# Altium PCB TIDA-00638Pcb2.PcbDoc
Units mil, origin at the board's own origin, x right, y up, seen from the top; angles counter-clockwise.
Board outline 1170 x 1290 mil, 4 copper layers (Top Layer, PowerLayer, GroundLayer, Bottom Layer), stack 84.834 mil thick; 44 components, 25 nets, 119 pads, 41 vias.
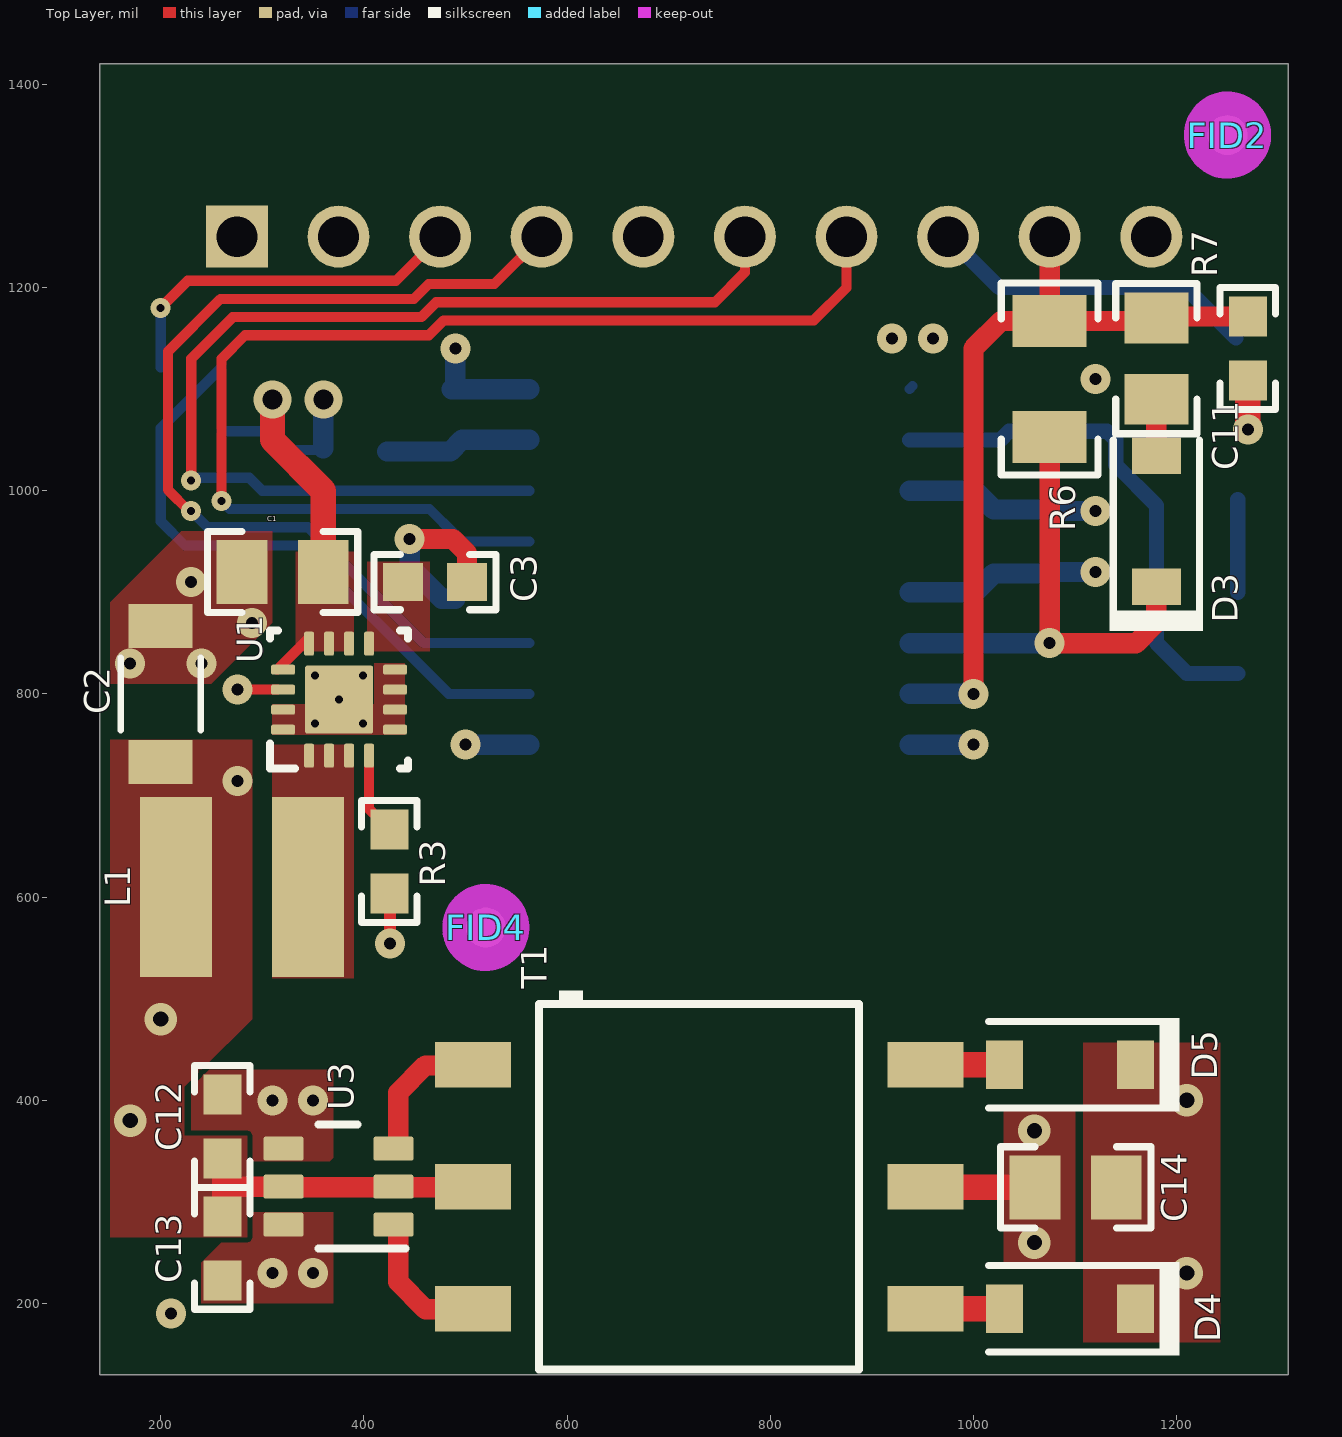
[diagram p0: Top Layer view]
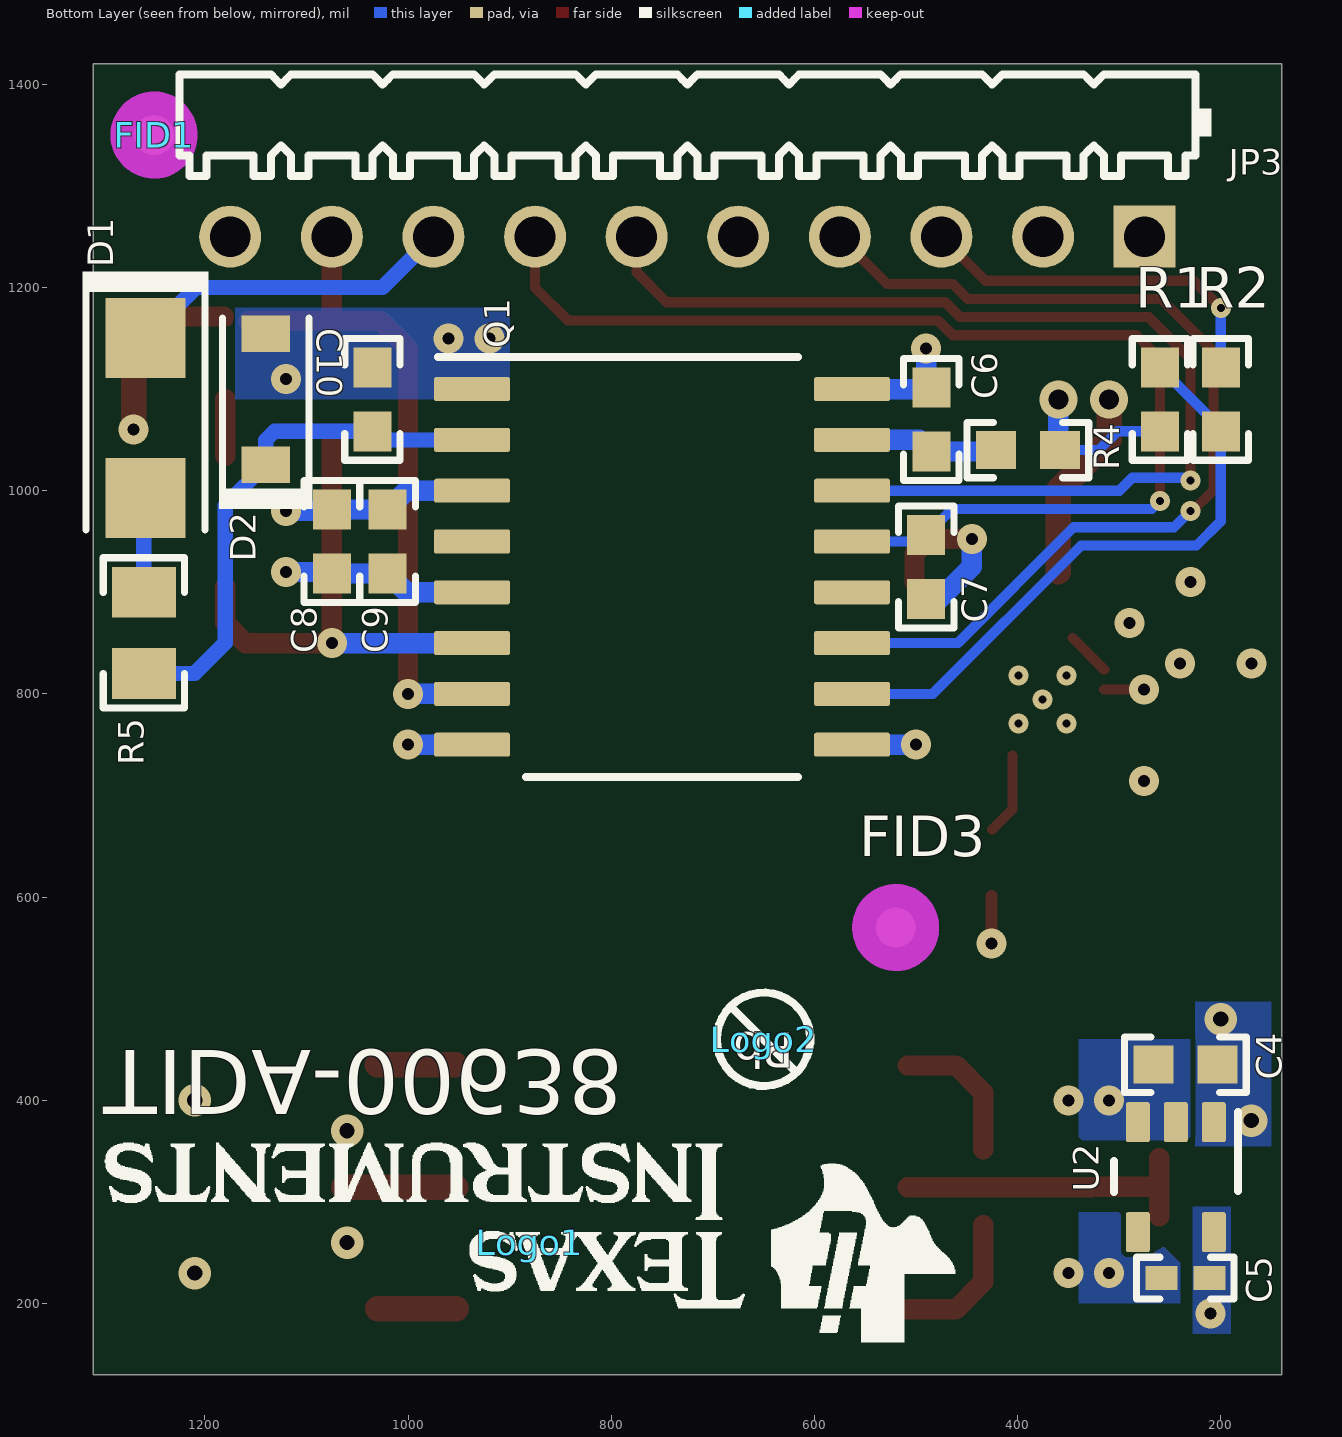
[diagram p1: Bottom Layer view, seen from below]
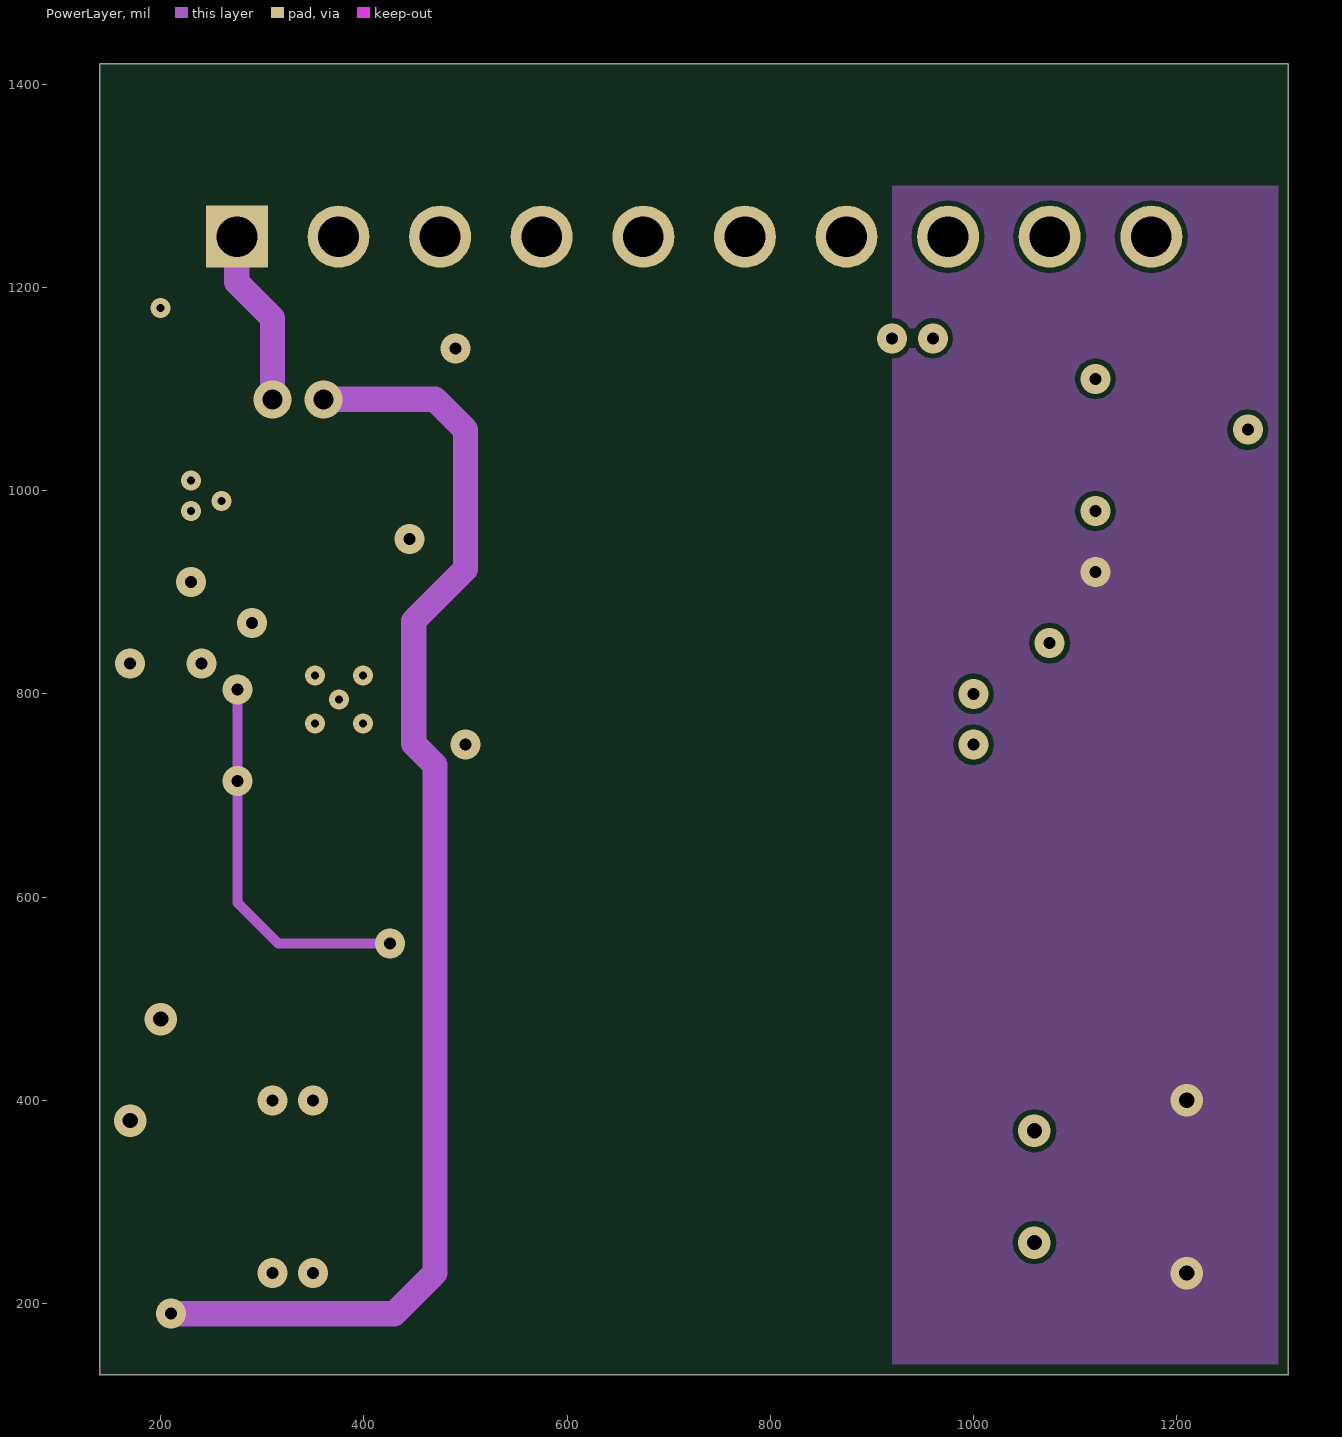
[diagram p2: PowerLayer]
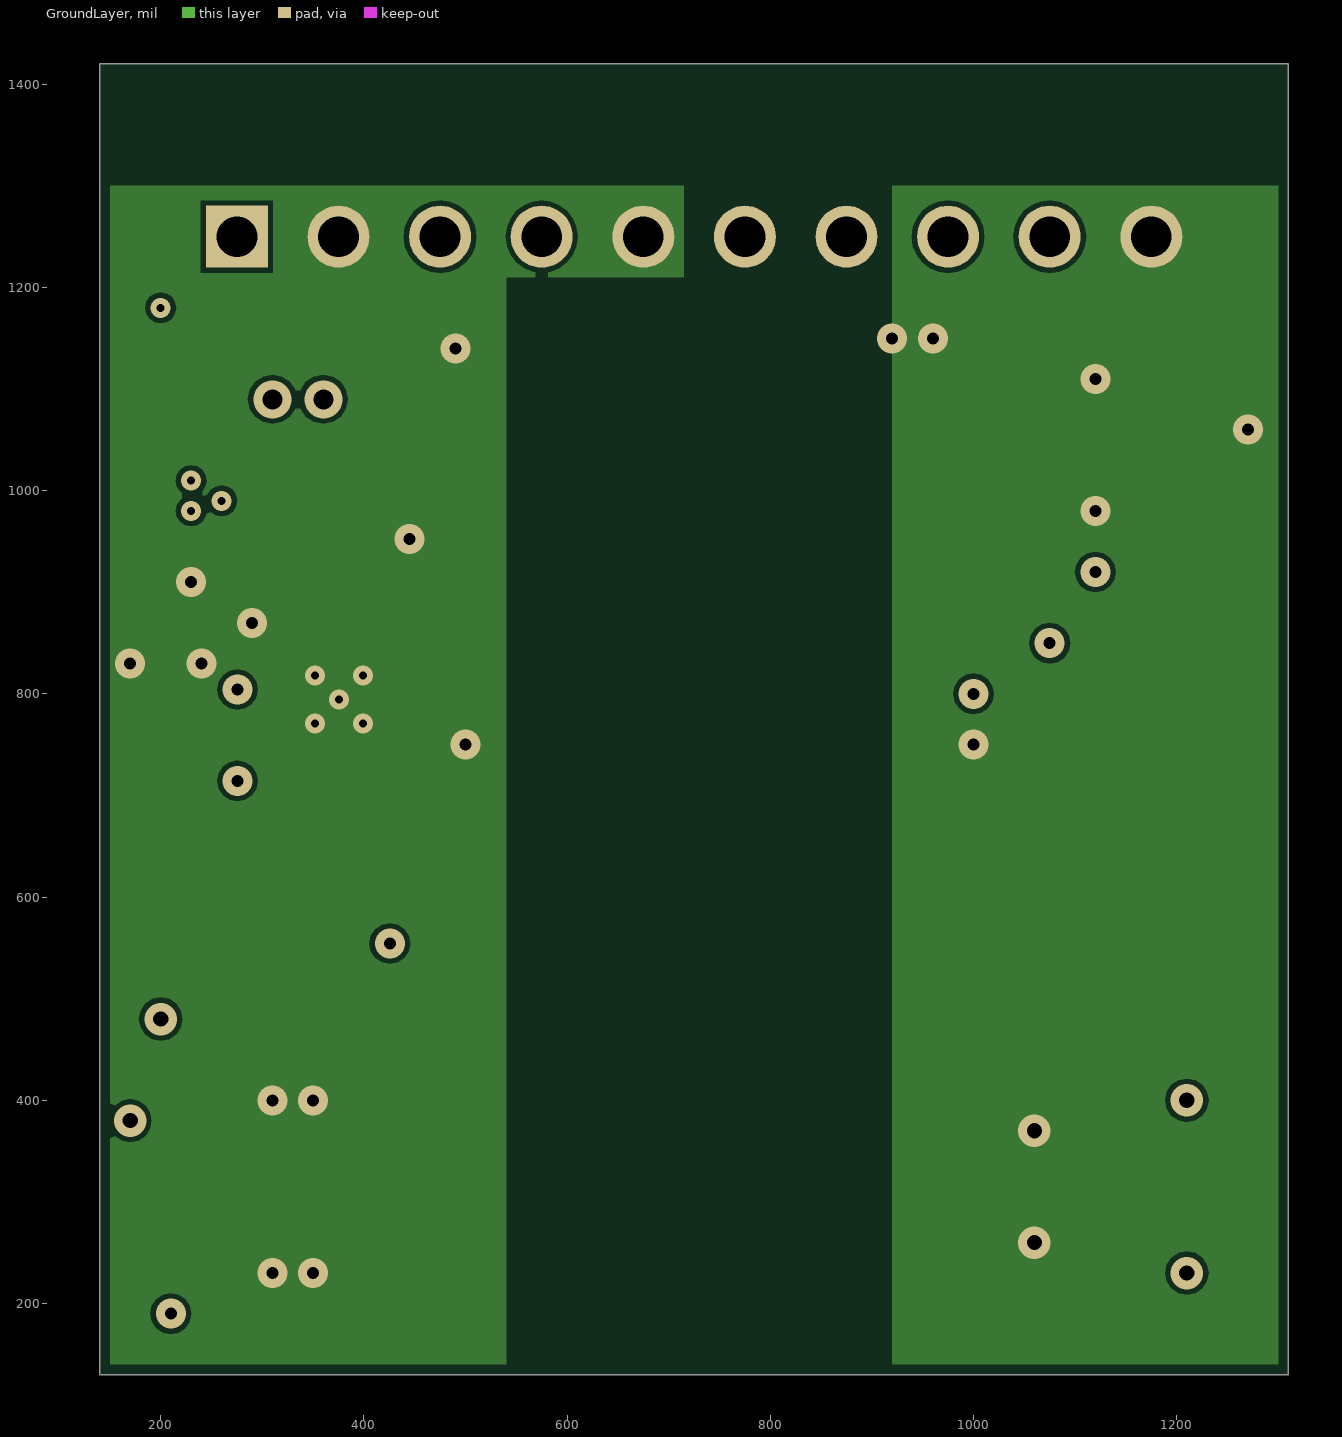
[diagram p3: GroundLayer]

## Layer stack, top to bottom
Top Solder: solder mask 0.4, Solder Resist, Dk 3.5
Top Layer: signal copper 1.4
Dielectric 2: dielectric 10, Dk 4.2
PowerLayer: signal copper 1.417
Dielectric1: core 59.2, FR-4, Dk 4.8
GroundLayer: signal copper 1.417
Dielectric 3: dielectric 10, Dk 4.2
Bottom Layer: signal copper 1.4
Bottom Solder: solder mask 0.4, Solder Resist, Dk 3.5

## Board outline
140,130 1310,130 1310,1420 140,1420

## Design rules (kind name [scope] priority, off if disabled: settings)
AcuteAngle [All] p1: minimum=4.50000000000000E+0001 checktracksonly=FALSE
AssemblyTestPointUsage [All] p1: valid=2
BoardOutlineClearance BoardOutlineClearance_MountingHoles [OnCopper and InComponentClass('Mounting Holes')] p1: gap=10
BoardOutlineClearance BoardOutlineClearance_Poly [OnCopper and IsPoly] p2: gap=10
BoardOutlineClearance [OnCopper and Not InComponentClass('Logo') and not InComponentClass('FiducialMark') and not InRegion(1000,500,4000,800) and not InPoly] p3: gap=10
Clearance Clearance_Keepouts [((IsTrack Or IsArc) And Not InPoly) And IsFree and IsKeepOut vs ((IsTrack Or IsArc) And Not InPoly) And IsFree and IsKeepOut] p1: gap=0
Clearance Clearance_Poly [InPolygon] p2: gap=5
Clearance [All] p3: gap=7.87
ComponentClearance ComponentClearance_MountingHoles_FiducialMarks [InComponentClass('Mounting Holes') vs InComponentClass('FiducialMark')] p1: gap=50 collisioncheckmode=3 verticalgap=10 showdistances=FALSE
ComponentClearance ComponentClearance_Shunt [InComponentClass('Header') vs InComponentClass('Shunt')] p2: gap=0 collisioncheckmode=3 verticalgap=0 showdistances=FALSE
ComponentClearance ComponentClearance_Logo [InComponentClass('Logo')] p3: gap=50 collisioncheckmode=3 verticalgap=10 showdistances=FALSE
ComponentClearance ComponentClearance_ScrewToNut [(HasFootprint('NY PMS 440 0025 PH')) vs (HasFootprint('Keystone_1902C'))] p4: gap=5 collisioncheckmode=3 verticalgap=10 showdistances=FALSE
ComponentClearance ComponentClearance_MountingHoles [InComponentClass('Mounting Holes')] p5: gap=250 collisioncheckmode=3 verticalgap=100000 showdistances=FALSE
ComponentClearance ComponentClearance_SmallPassives [HasFootprint('0201*') or HasFootprint('0402*') or HasFootprint('0508') or HasFootprint('0603*') or HasFootprint('0612') or HasFootprint('0805*') or HasFootprint('0815*') or HasFootprint('0830*') or HasFootprint('1206*') or HasFootprint('1210*') or HasFootprint('1808*') or HasFootprint('1812*') or HasFootprint('1825*') or HasFootprint('2010*') or HasFootprint('2220*') or HasFootprint('2225*') or HasFootprint('2512*') or HasFootprint('2728*') or HasFootprint('3518*') vs HasFootprint('0201*') or HasFootprint('0402*') or HasFootprint('0508') or HasFootprint('0603*') or HasFootprint('0612') or HasFootprint('0805*') or HasFootprint('0815*') or HasFootprint('0830*') or HasFootprint('1206*') or HasFootprint('1210*') or HasFootprint('1808*') or HasFootprint('1812*') or HasFootprint('1825*') or HasFootprint('2010*') or HasFootprint('2220*') or HasFootprint('2225*') or HasFootprint('2512*') or HasFootprint('2728*') or HasFootprint('3518*')] p6: gap=14.96 collisioncheckmode=3 verticalgap=10 showdistances=FALSE
ComponentClearance ComponentClearance_THtoSMT [IsThruComponent vs IsSMTComponent] p7: gap=40 collisioncheckmode=3 verticalgap=30 showdistances=FALSE
ComponentClearance ComponentClearance_THtoTH [IsThruComponent vs IsThruComponent] p8: gap=30 collisioncheckmode=3 verticalgap=30 showdistances=FALSE
ComponentClearance [All] p9: gap=30 collisioncheckmode=3 verticalgap=10 showdistances=FALSE
DiffPairsRouting [All] p1: maxlimit=100 minlimit=10 mostfreqgap=10 toplayer_minwidth=15 toplayer_maxwidth=15 toplayer_prefwidth=15 midlayer1_minwidth=15 midlayer1_maxwidth=15 midlayer1_prefwidth=15 midlayer2_minwidth=15 midlayer2_maxwidth=15 midlayer2_prefwidth=15 bottomlayer_minwidth=15 bottomlayer_maxwidth=15 bottomlayer_prefwidth=15 maxuncoupledlength=1000
FabricationTestPointUsage TestPointUsage [All] p1: valid=2 allowmultiple=FALSE
FabricationTestpoint Testpoint [All] p1: side=3 testpointundercomponent=TRUE minsize=40 maxsize=100 preferedsize=60 minholesize=0 maxholesize=40 preferedholesize=32 testpointgrid=1 allowsidetop=TRUE allowsidebottom=TRUE usegrid=TRUE gridtolerance=0.01
FanoutControl Fanout_LCC [IsLCC] p1: bgadir=Out bgaviamode=Centered fanoutstyle=Auto fanoutdirection=Alternating viagrid=1 // Fanout_LCC (Default Rule)
FanoutControl Fanout_BGA [IsBGA] p2: bgadir=Out bgaviamode=Centered fanoutstyle=Auto fanoutdirection=Alternating viagrid=1 // Fanout_BGA (Default Rule)
FanoutControl Fanout_Default [All] p4: bgadir=Out bgaviamode=Centered fanoutstyle=Auto fanoutdirection=Alternating viagrid=1 // Fanout_Default (Default Rule)
FanoutControl Fanout_Small [(CompPinCount < 5)] p5: bgadir=Out bgaviamode=Centered fanoutstyle=Auto fanoutdirection=OutThenIn viagrid=1 // Fanout_Small (Default Rule)
HoleSize [All] p1: absolutevalues=TRUE maxlimit=251 minlimit=7.87 maxpercent=80.000 minpercent=20.000
MinimumAnnularRing MinimumAnnularRing_ThermalPadVias [IsVia and InAnyComponent] p1: minimumring=5.91
MinimumAnnularRing [All] p2: minimumring=8
MinimumSolderMaskSliver MinimumSolderMaskSliver_Logo [InComponentClass('Logo') vs InComponentClass('Logo')] p1: minsoldermaskwidth=0.7
MinimumSolderMaskSliver [All] p2: minsoldermaskwidth=3.94
PlaneConnect [All] p1: planeconnectstyle=Direct reliefexpansion=10 reliefentries=4 reliefconductorwidth=10 reliefairgap=10
PolygonConnect [All] p1: connectstyle=Direct reliefconductorwidth=10 reliefentries=4 polygonreliefangle="90 Angle" airgapwidth=10
RoutingVias ThermalPadVias [IsVia and InAnyComponent] p1: holewidth=7.87 width=19.68 viastyle="Through Hole" minholewidth=7.87 minwidth=19.68 maxholewidth=12.99 maxwidth=23.62
RoutingVias [All] p2: holewidth=16 width=34 viastyle="Through Hole" minholewidth=7.87 minwidth=26 maxholewidth=40 maxwidth=65
SilkToBoardRegionClearance [Not ((IsComment or IsDesignator) And (Hide <> 'False')) and not InRegion(1000,500,4000,800)] p1:
SilkToSilkClearance SilkToSilkClearance_Pb-FreeLogo [(HasFootprint('Pb-Free_Overlay_Medium') OR HasFootprint('Pb-Free_Overlay_Small')) vs (HasFootprint('Pb-Free_Overlay_Medium') OR HasFootprint('Pb-Free_Overlay_Small'))] p1: silktosilkclearance=0
SilkToSilkClearance [All] p2: silktosilkclearance=4
SilkToSolderMaskClearance SilkToComponentPadClearance [(IsPad or IsFill or IsRegion) and InAnycomponent] p1: minsilkscreentomaskgap=5 clearancetoexposedcopper=TRUE
SilkToSolderMaskClearance "Silk to Solder Mask Opening" [All] p2: minsilkscreentomaskgap=4 clearancetoexposedcopper=FALSE
SolderMaskExpansion [All] p1: expansion=1.97
Width [All] p1: maxlimit=100 minlimit=6 preferedwidth=10 checkconnectedcopper=TRUE
15 further rules are at their usual default settings.

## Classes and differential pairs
component class Header: JP3
component class TIDA-00638Sch: C1 C2 C3 C4 C5 C6 C7 C8 C9 C10 C11 C12 C13 C14 D1 D2 D3 D4 D5 JP3 L1 Q1 R1 R2 R3 R4 R5 R6 R7 T1 U1 U2 U3
component class Logo: Logo1
component class EVM_Hardware: FID1 FID2 FID4 Logo1 Logo2 Logo3 ZZ1 ZZ2 ZZ3 ZZ4
component class FiducialMark: FID1 FID2 FID4
component class AssemblyNote: ZZ1 ZZ2 ZZ3 ZZ4

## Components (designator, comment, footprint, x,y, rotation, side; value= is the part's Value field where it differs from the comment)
C1 "GRM219R61E106KA12D" 0805_HV 320,920 r180 top
C2 "GRM31CR61A226KE19L" 1206_180 200,800 r90 top
C3 "GRM188R71E332KA01D" 0603#1 470,910 r0 top
C4 "CL10B105KQ8NNNC" 0603#1 235,435 r0 bottom
C5 "CL05A225KQ5NNNC" 0402 235,225 r0 bottom
C6 "C1608X7R1H104K080AA" 0603#1 485,1070 r90 bottom
C7 "06035A220JAT2A" 0603#1 490,925 r270 bottom
C8 "C1608X7R1H104K080AA" 0603#1 1075,950 r90 bottom
C9 "C1608X7R1V105K080AC" 0603#1 1020,950 r90 bottom
C10 "06035A221FAT2A" 0603#2 1410,1410 r180 bottom
C11 "GRM188R71H104KA93D" 0603#1 1270,1140 r270 top
C12 "GRM188R71H104KA93D" 0603#1 260.59,374.33 r90 top
C13 "C1608X5R1A106M080AC" 0603#1 260.59,254.33 r270 top
C14 "GRM21BR6YA106KE43L" 0805_HV 1100.59,314.33 r180 top
D1 "STTH112A" SMA 1258.46,1071.54 r270 bottom
D2 "1N5819HW-7-F" SOD-123 1140,1090 r90 bottom
D3 "1N5819HW-7-F" SOD-123 1180,970 r90 top
D4 "MBR0540T1G" SOD-123 1095,194.92 r180 top
D5 "MBR0540T1G" SOD-123 1095,435.08 r180 top
FID1 "Fiducial" Fiducial10-20 1250,1350 r180 bottom
FID2 "Fiducial" Fiducial10-20 1250,1350 r0 top
FID3 "Fiducial" Fiducial10-20 520,570 r180 bottom
FID4 "Fiducial" Fiducial10-20 520,570 r0 top
JP3 "TSW-110-08-T-S-RA" Samtec_TSW-110-08-x-S-RA 725,1250 r0 bottom
L1 "SDR0403-2R2ML" SDR0403 280,610 r180 top
Logo1 "Texas Instruments" TI_Stacked_Overlay_Small 880,260 r0 bottom
Logo2 "Pb-Free Symbol" Pb-Free_Overlay_Small 650,460 r0 bottom
Logo3 "FCC disclaimer" FCC_disclaimer 2350,3380 r0 top
Q1 "ISO5451DWR" DW0016B_N 750,925 r180 bottom
R1 "CRCW06030000Z0EA" 0603#1 260,1090 r270 bottom
R2 "CRCW06030000Z0EA" 0603#1 200,1090 r270 bottom
R3 "CRCW0603100KJNEA" 0603#1 425,635 r270 top
R4 "RC0603FR-0710RL" 0603#1 390,1040 r0 bottom
R5 "CRCW08051K00JNEA" 0805_HV 1260,860 r90 bottom
R6 "RC1206FR-074R7L" 1206 1075,1110 r90 top
R7 "RC0805JR-074R7L" 0805_HV 1180,1130 r90 top
T1 "750342879" Wurth_750342879 730,315 r0 top
U1 "TPS62143RGTT" RGT0016C 375.59,794.33 r90 top
U2 "TPS70633DBVR" DBV0005A_N 244.33,324.41 r270 bottom
U3 "SN6505ADBVR" DBV0006A_N 375,315 r180 top
ZZ1 "This Assembly Note is for PCB labels only" AssemblyNoteLabel 185,3938 r0 top
ZZ2 "These assemblies are ESD sensitive, ESD precautions shall be observed." AssemblyNote 185,3829.11 r0 top
ZZ3 "These assemblies must be clean and free from flux and all contaminants. Use of no clean flux is not acceptable." AssemblyNote 185,3740.56 r0 top
ZZ4 "These assemblies must comply with workmanship standards IPC-A-610 Class 2, unless otherwise specified." AssemblyNote 185,3652 r0 top

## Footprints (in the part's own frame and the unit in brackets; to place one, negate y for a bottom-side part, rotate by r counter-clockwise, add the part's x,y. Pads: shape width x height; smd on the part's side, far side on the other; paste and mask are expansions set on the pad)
0402 [mm] "0402 from SM-752 data"
  rect 0.8x0.6 smd: 1(-0.6,0) 2(0.6,0)
  silkscreen extent -1.22,-0.52 1.22,0.52, body extent -0.55,-0.3 0.55,0.3, height 0.6
0603#1 [mm] "0603 from SM-752 data"
  rect 1x0.95 smd: 1(-0.8,0) 2(0.8,0)
  silkscreen extent -1.52,-0.69 1.52,0.69, body extent -0.87,-0.47 0.87,0.47, height 1
0603#2 [mm] "0603 from SM-752 data"
  rect 0.95x1 smd: 1(9.525,-8.928) 2(9.525,-7.328)
  silkscreen extent 8.83,-9.65 10.22,-6.6, body extent 9.05,-9 10,-7.25, height 1
0805_HV [mil] "0805 with 30mil clearance between pads"
  rect 50x63 smd: 1(-40,0) 2(40,0)
  silkscreen extent -74,-40 74,40, body extent -43,-29 43,29, height 57
1206 [mm] "1206 from SM-752 data"
  rect 1.3x1.85 smd: 1(-1.45,0) 2(1.45,0)
  silkscreen extent -2.4,-1.21 2.4,1.21, body extent -1.7,-0.9 1.7,0.9, height 1.35
1206_180 [mm] "1206_180"
  rect 1.1x1.6 smd: 1(-1.7,0) 2(1.7,0)
  silkscreen extent -0.9,-1 0.9,1, body extent -1.75,-0.95 1.75,0.95, height 1.8
AssemblyNote [mil] "Assembly Note"
AssemblyNoteLabel [mil] "Assembly Note for PCB Labels"
DBV0005A_N [mm] "SOT23, 5-Leads, Body 2.9x1.6mm, Pitch 0.95mm, Lead Span 2.8mm, IPC Medium Density"
  rrect17% 1x0.6 smd: 1(-1.375,0.95) 2(-1.375,0) 3(-1.375,-0.95) 4(1.375,-0.95) 5(1.375,0.95)
  silkscreen extent -1.63,-1.55 0.38,1.55, body extent -1.42,-1.46 1.42,1.46, height 1.09
DBV0006A_N [mm] "SOT23, 6-Leads, Body 2.9x1.6mm, Pitch 0.95mm, Lead Span 2.8mm, IPC Medium Density"
  rrect17% 1x0.6 smd: 1(-1.375,0.95) 2(-1.375,0) 3(-1.375,-0.95) 4(1.375,-0.95) 5(1.375,0) 6(1.375,0.95)
  silkscreen extent -1.68,-1.55 0.5,1.55, body extent -1.42,-1.46 1.42,1.46, height 1.12
DW0016B_N [mm] "SOIC, 16-Leads, Body 10.5x7.6mm, Pitch 1.27mm, IPC Medium Density"
  rrect17% 1.9x0.6 smd: 1(-4.75,4.445) 2(-4.75,3.175) 3(-4.75,1.905) 4(-4.75,0.635) 5(-4.75,-0.635) 6(-4.75,-1.905) 7(-4.75,-3.175) 8(-4.75,-4.445) 9(4.75,-4.445) 10(4.75,-3.175) 11(4.75,-1.905) 12(4.75,-0.635) 13(4.75,0.635) 14(4.75,1.905) 15(4.75,3.175) 16(4.75,4.445)
  silkscreen extent -5.6,-5.25 3.4,5.25, body extent -5.17,-5.15 5.17,5.15, height 2.59
FCC_disclaimer [mil]
Fiducial10-20 [mm]
  round 1 smd mask+0.5: 1(0,0)
  Top Layer keep-out circle w1.178: c0,0 r0.5
Pb-Free_Overlay_Small [mil]
  silkscreen extent -46,-46 46,46
RGT0016C [mm] "QFN, 16-Leads, Body 3x3mm, Pitch 0.5mm, Thermal Pad 1.7x1.7mm, TI Recommended"
  rrect40% 0.6x0.25 smd: 1(-1.4,0.75) 2(-1.4,0.25) 3(-1.4,-0.25) 4(-1.4,-0.75) 9(1.4,-0.75) 10(1.4,-0.25) 11(1.4,0.25) 12(1.4,0.75)
  rrect40% 0.25x0.6 smd: 5(-0.75,-1.4) 6(-0.25,-1.4) 7(0.25,-1.4) 8(0.75,-1.4) 13(0.75,1.4) 14(0.25,1.4) 15(-0.25,1.4) 16(-0.75,1.4)
  rrect6% 1.55x1.55 on Top Paste: 17(0,0)
  rrect6% 1.7x1.7 smd paste-0.85: 17(0,0)
  silkscreen extent -1.72,-1.73 1.72,1.73, body extent -1.57,-1.57 1.58,1.58, height 1.01
Samtec_TSW-110-08-x-S-RA [mm] "Header, 2.54mm, 10x1, R/A, TH"
  rect 1.55x1.55 hole 1.02: 1(-11.43,0)
  round 1.55 hole 1.02: 2(-8.89,0) 3(-6.35,0) 4(-3.81,0) 5(-1.27,0) 6(1.27,0) 7(3.81,0) 8(6.35,0) 9(8.89,0) 10(11.43,0)
  silkscreen extent -13.1,-4.06 12.7,-1.52, body extent -12.7,-9.9 12.7,0.32, height 3.02
SDR0403 [mm] "BOURNS"
  rect 1.8x4.5 smd: 1(-1.65,0) 2(1.65,0)
  body extent -2.4,-2.4 2.4,2.4, height 3.3
SMA [mm] "Molded Diode, 2-Leads, Body 4.3x2.6mm, IPC Medium Density, based on OnSemi component dimensions and land pattern"
  rect 2x2 smd: 1(-2,0) 2(2,0)
  silkscreen extent -3.66,-1.57 2.79,1.57, body extent -2.6,-1.3 2.6,1.3, height 2.42
SOD-123 [mm] "On Semi recommended land pattern"
  rect 0.915x1.22 smd: 1(-1.637,0) 2(1.637,0)
  silkscreen extent -2.74,-1.17 2.03,1.17, body extent -1.93,-0.9 1.93,0.9, height 1.35
TI_Stacked_Overlay_Small [mil]
  silkscreen extent -418,-98 418,98
Wurth_750342879 [mm] "SMD, 6-Leads, Body 9.14x8mm, Pitch 3.05mm"
  rect 1.9x1.14 smd: 1(-5.655,3.05) 2(-5.655,0) 3(-5.655,-3.05) 4(5.655,-3.05) 5(5.655,0) 6(5.655,3.05)
  silkscreen extent -4,-4.57 4,4.9, body extent -6.35,-4.57 6.35,4.57, height 7.83

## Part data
C1: "CAP, CERM, 10 µF, 25 V, +/- 10%, X5R, 0805"
C2: "CAP, CERM, 22 µF, 10 V, +/- 10%, X5R, 1206"
C3: "CAP, CERM, 3300 pF, 25 V, +/- 10%, X7R, 0603"
C4: "CAP, CERM, 1 µF, 6.3 V, +/- 10%, X7R, 0603"
C5: "CAP, CERM, 2.2 µF, 6.3 V, +/- 10%, X5R, 0402"
C6 C8 C11 C12: "CAP, CERM, 0.1 µF, 50 V, +/- 10%, X7R, 0603"
C7: "CAP, CERM, 22 pF, 50 V, +/- 5%, C0G/NP0, 0603"
C9: "CAP, CERM, 1 µF, 35 V, +/- 10%, X7R, 0603"
C10: "CAP, CERM, 220 pF, 50 V, +/- 1%, C0G/NP0, 0603"
C13: "CAP, CERM, 10 µF, 10 V, +/- 20%, X5R, 0603"
C14: "CAP, CERM, 10 µF, 35 V, +/- 10%, X5R, 0805"
D1: "Diode, Ultrafast, 1200 V, 1 A, SMA"
D2 D3: "Diode, Schottky, 40 V, 1 A, SOD-123"
D4 D5: "Diode, Schottky, 40 V, 0.5 A, SOD-123"
FID1 FID2 FID3 FID4: "Fiducial mark.  There is nothing to buy or mount."
JP3: "Header, 2.54mm, 10x1, Tin, R/A, TH"
L1: "Inductor, Drum Core, Ferrite, 2.2 µH, 2.6 A, 0.047 ohm, SMD"
Logo1: library part TI_Logo, "Texas Instrument Corporate Signature"
Logo2: library part Pb-Free
Logo3: library part FCC_disclaimer, "FCC_disclaimer"
Q1: "High-CMTI 2.5-A / 5-A Isolated IGBT, MOSFET Gate Driver with Active Safety Features, DW0016B (SOIC-16)"
R1 R2: "RES, 0, 5%, 0.1 W, 0603"
R3: "RES, 100 k, 5%, 0.1 W, 0603"
R4: "RES, 10.0, 1%, 0.1 W, 0603"
R5: "RES, 1.0 k, 5%, 0.125 W, 0805"
R6: "RES, 4.70, 1%, 0.25 W, 1206"
R7: "RES, 4.7, 5%, 0.125 W, 0805"
T1: "Transformer, 50 uH, SMT"
U1: "Buck Step Down Regulator with 3 to 17 V Input and 5 V Output, -40 to 85 degC, 16-Pin QFN (RGT), Green (RoHS & no Sb/Br)"
U2: "150-mA, 6.5-V, 1-uA IQ Voltage Regulators with Enable, DBV0005A (SOT-5)"
U3: "Low-Noise 1-A Transformer Driver for Isolated Power Supplies, Internal Clock-160kHz, DBV0006A (SOT-6)"
ZZ1: library part AssemblyNoteLabel
ZZ2 ZZ3 ZZ4: library part AssemblyNote

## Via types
v1: diameter 29.53, hole 11.81, Top Layer to Bottom Layer, 24 vias
v2: diameter 32, hole 15, Top Layer to Bottom Layer, 6 vias
v3: diameter 19.68, hole 7.87, Top Layer to Bottom Layer, tented top, 5 vias
v4: diameter 19.68, hole 7.87, Top Layer to Bottom Layer, 4 vias
v5: diameter 37.4, hole 19.68, Top Layer to Bottom Layer, 2 vias

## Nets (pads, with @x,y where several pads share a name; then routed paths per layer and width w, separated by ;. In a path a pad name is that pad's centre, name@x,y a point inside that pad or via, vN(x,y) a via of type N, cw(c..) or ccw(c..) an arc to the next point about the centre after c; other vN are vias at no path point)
+3V3: C5.1 R1.2 R4.1 U2.5 | length 1445.6
  PowerLayer w25: v1(210,190) 430,190 470,230 470,730 449,751 449,871.76 500,922.76 500,1060 470,1090 v5(360,1090)
  Bottom Layer w10: R1.2 301.5,1058.5 320,1040 R4.1 R4.1@360,1041.5
  Bottom Layer w20: R4.1@360,1041.5 v5(360,1090)
+5V: C2.1 C4.1 C12.1 C13.1 L1.2 R3.2 T1.2 U1.14 U2.1 U3.2 U3.5 | length 760.3
  Top Layer w10: v1(275.59,804.33) 275.75,804.17 U1.14@314.76,804.17
  Top Layer w12: v1(425.59,554.33) R3.2@425.59,600.87
  Top Layer w20: C13.1 C12.1 ; 260.59,315 U3.5 ; U3.5@327.44,314.33 T1.2@508.09,314.33
  PowerLayer w10: v1(275.59,804.33) v1(275.59,714.33) 275.59,594.33 315.59,554.33 v1(425.59,554.33)
  other v2: 170,380 200,480
+15V: C1.1 JP3.1 U1.10 U1.11 U1.12 U1.13 | length 409.5
  Top Layer w10: U1.13@314.76,823.86 U1.12@346.06,855.16
  Top Layer w25: v5(310,1090) 310,1050 360,1000 C1.1
  PowerLayer w25: JP3.1 275,1205 310,1170 v5(310,1090)
+15VI: C8.1 C9.1 C14.1 D4.1 D5.1 Q1.5 | length 191.3
  Bottom Layer w10: C8.1@1070,918.5 C8.1@1071.5,920
  Bottom Layer w20: Q1.5 1001.5,900 C9.1 C8.1@1070,918.5 ; C8.1@1071.5,920 v1(1120,920)
  other v2: 1210,230 1210,400
DESAT: C10.1 D2.1 Q1.2 R5.1 | length 519
  Bottom Layer w15: Q1.2 1026.5,1050 C10.1 1131.5,1058.5 1140,1050 D2.1 1180,985.53 1180,850 1210,820 R5.1
FAULT: C7.1 JP3.7 Q1.13 | length 1153.7
  Top Layer w10: v4(260,990) 260,1130 282.99,1152.99 463.91,1152.99 478.55,1167.64 842.86,1167.64 875,1199.78 JP3.7
  Bottom Layer w10: v4(260,990) 268,982 464.5,982 C7.1 496.5,950 Q1.13
GND: C1.2 C2.2 C3.2 C4.2 C5.2 C6.2 C7.2 C12.2 C13.2 JP3.2 JP3.5 Q1.9 Q1.16 U1.5 U1.6 U1.7 U1.8 U1.15 U1.16 U1.17@375.59,794.33 U2.2 U2.3 U3.4 U3.6 | length 357.3
  Top Layer w20: v1(445,952.5) 487.5,952.5 501.5,938.5 C3.2
  Bottom Layer w10: C6.2@486.5,1100 C6.2@490,1103.5
  Bottom Layer w20: v1(445,952.5) 445,925 476.5,893.5 C7.2 ; C6.2@486.5,1100 Q1.16 ; C6.2@490,1103.5 v1(490,1140) ; v1(500,750) Q1.9
  other v1: 310,230 350,230 310,400 350,400 170,830 240,830 290,870 230,910
  other v3: 351.97,770.71 399.21,770.71 375.59,794.33 351.97,817.95 399.21,817.95
GNDI: C8.2 C9.2 C10.2 C11.2 C14.2 D2.2 JP3.10 Q1.1 Q1.3 Q1.8 T1.5 | length 417.1
  Top Layer w25: T1.5@953.09,314.33 C14.2@1063.19,314.33 ; v1(1270,1060) C11.2
  Bottom Layer w10: Q1.1 Q1.1@940,1102.99 ; C8.2@1070,981.5 C8.2@1071.5,980
  Bottom Layer w20: Q1.8 v1(1000,750) ; Q1.3 1001.5,1000 C9.2 C8.2@1070,981.5 ; C8.2@1071.5,980 v1(1120,980)
  other v1: 1120,1110 920,1150 960,1150
  other v2: 1060,260 1060,370
GTDRV: C11.1 JP3.9 Q1.7 R6.2 R7.2 | length 746.8
  Top Layer w10: R7.2@1177.09,1167.09 R7.2
  Top Layer w20: v1(1000,800) 1000,1140 1027.09,1167.09 R6.2 ; JP3.9 R6.2 ; R7.2@1157.09,1167.09 R6.2 ; R7.2@1181.5,1171.5 C11.1
  Bottom Layer w20: Q1.7 v1(1000,800)
NetC3_1: C3.1 U1.9
NetC6_1: C6.1 Q1.15 R4.2 | length 146.9
  Bottom Layer w10: R4.2 R4.2@422.99,1038.5
  Bottom Layer w20: R4.2@422.99,1038.5 C6.1 496.5,1050 Q1.15
NetD1_2: D1.2 R5.2 | length 93.4
  Bottom Layer w10: D1.2 D1.2@1260,991.26
  Bottom Layer w15: R5.2 D1.2@1260,991.26
NetD3_2: D3.2 R7.1 | length 55.5
  Top Layer w20: D3.2 R7.1
NetD4_2: D4.2 T1.4 | length 77.1
  Top Layer w25: T1.4 D4.2@1029.78,194.92
NetD5_2: D5.2 T1.6 | length 77.3
  Top Layer w25: T1.6@953.23,435.08 D5.2
NetL1_1: L1.1 U1.1 U1.2 U1.3
NetR3_1: R3.1 U1.4 | length 81
  Top Layer w10: U1.4 405.12,686.38 R3.1
NetT1_1: T1.1 U3.3 | length 141.2
  Top Layer w20: U3.3@433.74,351.73 433.74,407.48 460.59,434.33 T1.1@508.09,434.33
NetT1_3: T1.3 U3.1 | length 141.2
  Top Layer w20: U3.1@433.74,276.93 433.74,221.18 460.59,194.33 T1.3@508.09,194.33
OUT: D3.1 Q1.6 R6.1 | length 489.7
  Top Layer w20: R6.1 v1(1075,850) 1160,850 1180,870 D3.1
  Bottom Layer w20: Q1.6 v1(1075,850)
PWM1: JP3.3 R2.1 | length 362.5
  Top Layer w10: v4(200,1180) 226.61,1206.61 431.61,1206.61 JP3.3
  Bottom Layer w10: R2.1 v4(200,1180)
PWM1.1: Q1.10 R1.1 R2.2 | length 609.8
  Bottom Layer w10: R1.1 200,1061.5 R2.2 200,970 223.87,946.13 337.42,946.13 483.54,800 Q1.10
PWM2: JP3.4 Q1.11 | length 969.2
  Top Layer w10: v4(230,980) 227.87,980 207.28,1000.59 207.28,1137.28 258.74,1188.74 449.1,1188.74 463.74,1203.39 528.39,1203.39 JP3.4
  Bottom Layer w10: v4(230,980) 246,964 345,964 459,850 Q1.11
QCOL: D1.1 JP3.8 | length 324.8
  Bottom Layer w15: JP3.8 1025,1200 1208.74,1200 D1.1
RST: JP3.6 Q1.14 | length 1074.6
  Top Layer w10: v4(230,1010) 230,1130 270.87,1170.87 456.5,1170.87 471.15,1185.51 745.51,1185.51 775,1215 JP3.6
  Bottom Layer w10: v4(230,1010) 232.72,1012.72 287.28,1012.72 300,1000 Q1.14
pads on no net: FID1.1 FID2.1 FID3.1 FID4.1 Q1.4 Q1.12 U1.17@375.59,794.33 U2.4

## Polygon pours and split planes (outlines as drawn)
GNDI on Top Layer "TOP_LAYER_GNDI_P038" (solid, remove dead copper, pour order 38): 1030,390 1100,390 1100,240 1030,240
NetL1_1 on Top Layer "TOP_LAYER_NETL1_1_P034" (solid, remove dead copper, pour order 34): 390,750 390,520 310,520 310,750
GND on Top Layer "Top-GND 2" (solid, remove dead copper, pour order 32): 230,340 370,340 370,430 230,430
GND on Top Layer "TOP_LAYER_GND_P030" (solid, remove dead copper, pour order 30): 240,200 370,200 370,290 290,290 240,240
GND on Top Layer "TOP_LAYER_GND_P026" (solid, remove dead copper, pour order 26): 250,810 150,810 150,890 220,960 310,960 310,870 280,840
+5V on Top Layer "Top-N$6" (solid, remove dead copper, pour order 14): 150,755 290,755 290,480 223.17,413.17 223.17,365 285,365 285,265 223.17,265 150,265
+15VI on Top Layer "Top-+15VI" (solid, remove dead copper, pour order 10): 1108.09,456.83 1243.09,456.83 1243.09,161.83 1108.09,161.83
NetC3_1 on Top Layer "Top-N$3" (solid, remove dead copper, pour order 4): 403.09,841.83 403.09,930 465,930 465,841.83
+15V on Top Layer "Top-+15V" (solid, remove dead copper, pour order 0): 390,841.83 390,940 333.09,940 333.09,841.83
GND on Top Layer "TOP_LAYER_GND_P040" (solid, remove dead copper, pour order 40): 310,760 310,790 340,790 410,790 410,830 440,830 440,760
GND on Bottom Layer "BOTTOM_LAYER_GND_P028" (solid, remove dead copper, pour order 28): 240,200 340,200 340,290 290,290 240,240
+5V on Bottom Layer "Top-+5V" (solid, remove dead copper, pour order 24): 225,496.96 225,355 195,355 150,355 150,496.96
+3V3 on Bottom Layer "Top-+3V3" (solid, remove dead copper, pour order 22): 190,170 190,295 227.5,295 227.5,170
GND on Bottom Layer "Top-GND 2" (solid, remove dead copper, pour order 20): 229.96,360.62 254.96,360.62 340,360.62 340,460 229.96,460
GNDI on Bottom Layer "BOTTOM_LAYER_GNDI_P042" (solid, remove dead copper, pour order 42): 900,1090 900,1180 1170,1180 1170,1090
GNDI on GroundLayer "Top-GNDI" (solid, remove dead copper, pour order 8): 1340,130 920,130 920,1300 1340,1300
GND on GroundLayer "Bottom-GND" (solid, remove dead copper, pour order 16): 140,1300 715,1300 715,1210 540,1210 540,130 140,130
+15VI on PowerLayer "Top-GNDI" (solid, remove dead copper, pour order 36): 1310,130 920,130 920,1300 1310,1300

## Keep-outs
Keep-Out Layer:
  text ".Layer_Name" at 577,-858.49 h60

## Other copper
Top Layer:
  text ".Layer_Name" at 577,-858.49 h60
Bottom Layer:
  text ".Layer_Name" at 577,-858.49 h60

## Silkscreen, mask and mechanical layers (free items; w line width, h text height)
Top Overlay:
  text ".Layer_Name" at 577,-858.49 h60
Bottom Overlay:
  text "TIDA-00638" at 1300,470 h108.27 r180
  text ".Layer_Name" at 577,-858.49 h60
Top Paste:
  text ".Layer_Name" at 577,-858.49 h60
Bottom Paste:
  text ".Layer_Name" at 577,-858.49 h60
Top Solder:
  text ".Layer_Name" at 577,-858.49 h60
  text ".Layer_Name" at 577,-858.49 h60
Bottom Solder:
  text ".Layer_Name" at 577,-858.49 h60
Drill Guide:
  text ".Layer_Name" at 577,-858.49 h60
M1 Board Outline:
  lines w10: 1340,1410 1340,0 0,0 0,1410 1340,1420
  text ".Layer_Name" at 577,-858.49 h60
M2 Board Dimensions:
  rectangle: 0,-275 125,-150
  rectangle: 125,-400 500,-275
  lines w7: 0,-275 1000,-275 ; 125,-400 125,-150 ; 250,-400 250,-150 ; 500,-400 500,-150 ; 750,-400 750,-150 ; 0,-400 1000,-400 1000,-150 0,-150 0,-400
  text ".Layer_Name" at 577,-858.49 h60
M3 3D STEP Top:
  text ".Layer_Name" at 577,-858.49 h60
M4 3D STEP Bottom:
  text ".Layer_Name" at 577,-858.49 h60
M5 Assembly Top:
  lines w10: -292,-930.17 6308,-930.17 ; -292,-726.83 6310,-726.83 ; -292,-523.5 -292,-1133.5 3713,-1133.5 6310,-1133.5 6310,-523.5 -291.5,-523.5 -291.5,-1133.5 1284,-1133.5 ; 2173,-1133.5 2173,-523.5 ; 3440,-726.83 3440,-523.5 ; 4280,-726.83 4280,-523.5 ; 4902,-1140 4902,-937.17
  text "COMPONENTS MARKED 'DNP' SHOULD NOT BE POPULATED." at 1153.5,-318.5 h60
  text "ASSEMBLY VARIANT:" at 1153,-434 h60
  text ".VariantName" at 2189,-434 h60
  text "PCB VIEWED FROM TOP SIDE" at -228.5,-655.67 h60
  text "BOARD #:" at 2248,-655.67 h60
  text ".PRJ_Number" at 2793.5,-655.67 h60
  text "REV:" at 3638,-655.67 h60
  text ".PCB_Rev" at 3929.5,-655.67 h60
  text "SVN REV:" at 4476,-655.67 h60
  text ".VersionControl_RevNumber" at 4982,-655.67 h60
  text "TID #:" at 2248,-859 h60
  text ".TID" at 2793.5,-859 h60
  text "PLOT NAME =" at -228.5,-1064.34 h60
  text ".plot_File_Name" at 577,-1064.34 h60
  text "GENERATED    :" at 2250,-1064.34 h60
  text ".Print_Date" at 3119.5,-1064.34 h60
  text ".Print_Time" at 3848.5,-1064.34 h60
  text "TEXAS INSTRUMENTS" at 5113,-1064.34 h60
M6 Assembly Bottom:
  lines w10: -292.5,-727.33 6309.5,-727.33 ; -290.5,-930.67 6309.5,-930.67 ; 1115.5,-1140.5 1115.5,-937.67 ; 1737.5,-727.33 1737.5,-524 ; 2577.5,-727.33 2577.5,-524 ; 3844.5,-1134 3844.5,-524 ; 4733.5,-1134 6309,-1134 6309,-524 -292.5,-524 -292.5,-1134 2304.5,-1134 6309.5,-1134 6309.5,-524
  text "COMPONENTS MARKED 'DNP' SHOULD NOT BE POPULATED." at 6102,-318 h60
  text ".VariantName" at 5058,-434 h60
  text "ASSEMBLY VARIANT:" at 6097,-434 h60
  text ".VersionControl_RevNumber" at 1035.5,-656.17 h60
  text "SVN REV:" at 1541.5,-656.17 h60
  text ".PCB_Rev" at 2088,-656.17 h60
  text "REV:" at 2379.5,-656.17 h60
  text ".PRJ_Number" at 3224,-656.17 h60
  text "BOARD #:" at 3769.5,-656.17 h60
  text "PCB VIEWED FROM BOTTOM SIDE" at 6246,-656.17 h60
  text ".TID" at 3224,-859.5 h60
  text "TID #:" at 3769.5,-859.5 h60
  text "TEXAS INSTRUMENTS" at 904.5,-1064.84 h60
  text ".Print_Time" at 2169,-1064.84 h60
  text ".Print_Date" at 2898,-1064.84 h60
  text "GENERATED    :" at 3767.5,-1064.84 h60
  text ".plot_File_Name" at 5440.5,-1064.84 h60
  text "PLOT NAME =" at 6246,-1064.84 h60
M9 Title Sheet:
  drawing of 57 lines, arcs and shapes, not listed
  text "1" at 739.84,8036.5 h70
  text "2" at 3235.5,8036.5 h70
  text "3" at 5724.84,8036.5 h70
  text "4" at 8231.51,8036.5 h70
  text "5" at 10730.5,8036.5 h70
  text "6" at 13235.5,8036.5 h70
  text "A" at -416.5,6893.5 h70
  text "A" at 14383.5,6893.5 h70
  text "B" at -416.5,4513.5 h70
  text "B" at 14383.5,4513.5 h70
  text "C" at -416.5,2138.5 h70
  text "C" at 14383.5,2138.5 h70
  text "PROJECT TITLE:" at 11343.5,277.5 h45
  text ".PRJ_Title" at 11393.5,144.17 h70
  text "DESIGNED FOR:" at 11343.5,-23.5 h45
  text ".PRJ_Customer" at 11393.5,-163.5 h70
  text "D" at -416.5,-231.5 h70
  text "D" at 14383.5,-231.5 h70
  text "FILE NAME:" at 11343.5,-323.5 h45
  text ".PCB_File_Name_No_Path" at 11393.5,-443.5 h70
  text "Texas Instruments (TI) and/or its licensors do not warrant the accuracy or completeness of this specification" at 6374,-605.34 h45
  text "ENGINEER:" at 11343.5,-613.5 h45
  text "LAYOUT BY:" at 12848.5,-613.5 h45
  text "or any information contained therein. TI and/or its licensors do not warrant that this design will meet" at 6329.01,-718 h45
  text ".PRJ_Engineer" at 11393.5,-768.49 h70
  text ".PCB_Layout" at 12899,-768.49 h70
  text "the specifications, will be suitable for your application or fit for any particular purpose, or will operate in" at 6329.01,-830.67 h45
  text ".Layer_Name" at 577,-858.49 h60
  text "ALTIUM DESIGNER VERSION:" at 12848.5,-923.5 h45
  text "an implementation. TI and/or its licensors do not warrant that the design is production worthy. You should" at 6329.01,-943.33 h45
  text "completely validate and test your design implementation to confirm the system functionality for your application." at 6374,-1056 h45
  text ".print_Scale" at 11393.5,-1056.83 h70
  text ".Application_BuildNumber" at 12899,-1056.83 h70
  text "1" at 739.84,-1263.5 h70
  text "2" at 3235.5,-1263.5 h70
  text "3" at 5724.84,-1263.5 h70
  text "4" at 8231.51,-1263.5 h70
  text "5" at 10730.5,-1263.5 h70
  text "6" at 13235.5,-1263.5 h70
M10 Fab Notes:
  drawing of 173 lines, arcs and shapes, not listed
  text "DESIGN INFORMATION" at 12378.02,6201 h60
  text "MIN. TRACK WIDTH:" at 11733.46,6021 h60
  text "8" at 12829.7,6021 h60
  text "MIL" at 12984.46,6021 h60
  text "MIN. CLEARANCE:" at 11733.46,5889 h60
  text "0.2" at 12769.7,5889 h60
  text "mm" at 12984.46,5889 h60
  text "MIN. VIA PAD SIZE:" at 11733.46,5757 h60
  text "24" at 12799.71,5757 h60
  text "MIL" at 12984.46,5757 h60
  text "0.05mm (2MIL)" at 12428.46,5615.29 h60
  text "MINIMUM ANNULAR RING" at 11404.23,5611 h60
  text "EXTERNAL" at 13136.46,5611 h60
  text "PER" at 11604.23,5493 h60
  text "IPC-D-275 CLASS 2 LEVEL C" at 11824.23,5493 h60
  text "MIL, HOLES" at 13312.46,5380.71 h60
  text "+/-" at 12920,5380 h60
  text "+/-" at 13774,5380 h60
  text "REGISTRATION TOLERANCES:" at 11404.23,5375 h60
  text "METAL" at 12604,5375 h60
  text "5" at 13180.2,5375 h60
  text "3" at 14013.2,5375 h60
  text "MIL" at 14129.46,5375 h60
  text "+/-" at 13774,5262 h60
  text "HOLE SIZE TOLERANCE (UNLESS OTHERWISE SPECIFIED):" at 11404.23,5257 h60
  text "3" at 14013.2,5257 h60
  text "MIL" at 14129.46,5257 h60
  text "MATERIAL:" at 11329.46,5047.54 h60
  text "FR-4 High Tg" at 12315.9,4907.21 h60
  text "FR-408" at 11750.46,4898.64 h60
  text "OTHER" at 13238.46,4898.64 h60
  text "X" at 12161,4895 h60
  text "62 MIL (1.6mm) +/-10%" at 12070.56,4735.92 h60
  text "THICKNESS:" at 11404.23,4731.64 h60
  text "X" at 11942.4,4731.64 h60
  text "OTHER" at 13355.46,4731.64 h60
  text "TOLERANCE:" at 11404.23,4573.64 h60
  text "X" at 12243.53,4573.64 h60
  text "ANSI IPC-6012 TYPE 3 CLASS 2" at 12430.48,4573.64 h60
  text "OTHER +/-" at 12430.46,4417.64 h60
  text "BOW & TWIST:" at 11404.23,4260.64 h60
  text "X" at 12243.53,4260.64 h60
  text "ANSI IPC-6012 TYPE 3 CLASS 2" at 12430.48,4260.64 h60
  text "OTHER +/-" at 12430.46,4102.13 h60
  text "DRILLING:" at 11329.46,3963.64 h60
  text "REFERENCE:" at 11404.23,3846.64 h60
  text "X" at 12052.46,3846.64 h60
  text "AS SHOWN" at 12239.46,3846.64 h60
  text "X" at 12953.46,3846.64 h60
  text "NC_DRILL FILES" at 13090.46,3846.64 h60
  text "PTH COPPER THICKNESS:" at 11404.23,3688.64 h60
  text "X" at 12534.46,3688.64 h60
  text "20-30 um" at 12671.46,3688.64 h60
  text "OTHER" at 13388.46,3688.64 h60
  text "BOARD FINISH:" at 11329.46,3529.64 h60
  text "SILKSCREEN:" at 11484.68,3411.64 h60
  text "X" at 12433.46,3411.64 h60
  text "TOP" at 12559.46,3411.64 h60
  text "X" at 12943.46,3411.64 h60
  text "BOTTOM" at 13070.46,3411.64 h60
  text "SILKSCREEN COLOR:" at 11484.68,3244.64 h60
  text "X" at 12432.42,3244.64 h60
  text "WHITE" at 12559.46,3244.64 h60
  text "OTHER" at 13070.46,3244.64 h60
  text "X" at 12563.42,3085.44 h60
  text "GREEN" at 12690.46,3085.44 h60
  text "OTHER" at 13308.46,3085.44 h60
  text "SOLDER RESIST COLOR:" at 11484.68,3074.64 h60
  text "X" at 12563.42,2915.44 h60
  text "MATTE" at 12690.46,2915.44 h60
  text "SEMI-GLOSS" at 13308,2914.8 h60
  text "IMMERSION GOLD (ENIG)" at 12390.46,2726.92 h60
  text "ENEPIG" at 13728,2723.64 h60
  text "SURFACE FINISH:" at 11329.46,2722.64 h60
  text "X" at 12203.51,2722.64 h60
  text "IMM. TIN/SILVER OR EQUIV" at 11659,2565.64 h60
  text "OTHER" at 13090.46,2565.64 h60
  text "ARRAY/PANEL:" at 11329.46,2386.64 h60
  text "CUT AND TRIM PER M1 BOARD OUTLINE" at 12390.46,2382.35 h60
  text "N.C. ROUTE" at 12390.46,2230.64 h60
  text "X" at 13069.46,2230.64 h60
  text "V. SCORE" at 13256.46,2230.64 h60
  text "CERTIFICATION:" at 11329.46,2093.64 h60
  text "MATERIALS AND WORKMANSHIP FOR ALL PCBS" at 12054.46,2093.64 h60
  text "TO MEET OR EXCEED THE REQUIREMENTS OF:" at 12054.46,1995.64 h60
  text "X" at 11680.96,1859.13 h60
  text "ANSI IPC-A-600F CLASS ->" at 11819.96,1859.13 h60
  text "X" at 13459.02,1859.13 h60
  text "2" at 13577.96,1859.14 h60
  text "1" at 13262.96,1857.64 h60
  text "3" at 13931.96,1857.64 h60
  text "X" at 12495.02,1699.64 h60
  text "RoHS" at 12631.96,1699.64 h60
  text "OTHER" at 13276.36,1699.64 h60
  text "PER ORDER" at 13673.42,1699.64 h60
  text "ALL BOARDS MUST MEET OR EXCEED UL94-V0 REQUIREMENTS." at 11357,1534 h60
  text "PCB MUST BEAR THE UL94V-0 UL REGISTERED MATERIAL ID NUMBER" at 11357,1414 h60
  text "ADDITIONAL REQUIREMENTS:" at 11329.46,1240.64 h60
  text "MICROSECTION:" at 11404.23,1125.64 h60
  text "YES" at 12309.96,1125.64 h60
  text "REQUIRED" at 13171.46,969.49 h60
  text "BARE BOARD ELEC. TEST:" at 11404.23,966.64 h60
  text "NONE" at 12709.96,966.64 h60
  text "X" at 13044.46,966.64 h60
  text "PER ORDER" at 13763.46,966.64 h60
  text ".Layer_Name" at 577,-858.49 h60
M11 Gerber Information:
  lines w10: -292,-930.17 6308,-930.17 ; -292,-726.83 6310,-726.83 ; -292,-523.5 -292,-1133.5 3713,-1133.5 6310,-1133.5 6310,-523.5 -291.5,-523.5 -291.5,-1133.5 1284,-1133.5 ; 2173,-1133.5 2173,-523.5 ; 3440,-726.83 3440,-523.5 ; 4280,-726.83 4280,-523.5 ; 4902,-1140 4902,-937.17
  text "ALL ARTWORK VIEWED FROM TOP SIDE" at -228.5,-655.67 h60
  text "BOARD #:" at 2248,-655.67 h60
  text ".PRJ_Number" at 2793.5,-655.67 h60
  text "REV:" at 3638,-655.67 h60
  text ".PCB_Rev" at 3929.5,-655.67 h60
  text "SVN REV:" at 4476,-655.67 h60
  text ".VersionControl_RevNumber" at 4982,-655.67 h60
  text "LAYER NAME =" at -228.5,-858.49 h60
  text "TID #:" at 2248,-859 h60
  text ".TID" at 2793.5,-859 h60
  text "PLOT NAME =" at -228.5,-1064.34 h60
  text ".plot_File_Name" at 577,-1064.34 h60
  text "GENERATED    :" at 2250,-1064.34 h60
  text ".Print_Date" at 3119.5,-1064.34 h60
  text ".Print_Time" at 3848.5,-1064.34 h60
  text "TEXAS INSTRUMENTS" at 5113,-1064.34 h60
M12 Stackup:
  drawing of 191 lines, arcs and shapes, not listed
  text "Layer" at 9790.34,7830 h60
  text "Name" at 10200.26,7830 h60
  text "Material" at 11130,7830 h60
  text "Thickness" at 11989.77,7830 h60
  text "Constant" at 12639.6,7830 h60
  text "Board Layer Stack" at 13209.46,7830 h60
  text "1" at 9790.34,7710 h60
  text "Top Overlay" at 10200.26,7710 h60
  text "2" at 9790.34,7590 h60
  text "Top Solder" at 10200.26,7590 h60
  text "Solder Resist" at 11130,7590 h60
  text "0.40mil" at 11989.77,7590 h60
  text "3.5" at 12639.6,7590 h60
  text "3" at 9790.34,7470 h60
  text "Top Layer" at 10200.26,7470 h60
  text "Copper" at 11130,7470 h60
  text "1.40mil" at 11989.77,7470 h60
  text "4" at 9790.34,7350 h60
  text "Dielectric1" at 10200.26,7350 h60
  text "FR-4" at 11130,7350 h60
  text "59.20mil" at 11989.77,7350 h60
  text "4.8" at 12639.6,7350 h60
  text "5" at 9790.34,7230 h60
  text "Bottom Layer" at 10200.26,7230 h60
  text "Copper" at 11130,7230 h60
  text "1.40mil" at 11989.77,7230 h60
  text "6" at 9790.34,7110 h60
  text "Bottom Solder" at 10200.26,7110 h60
  text "Solder Resist" at 11130,7110 h60
  text "0.40mil" at 11989.77,7110 h60
  text "3.5" at 12639.6,7110 h60
  text "7" at 9790.34,6990 h60
  text "Bottom Overlay" at 10200.26,6990 h60
  text ".Layer_Name" at 577,-858.49 h60
M13 Component Bodies Top:
  text ".Layer_Name" at 577,-858.49 h60
M14 Component Bodies Bottom:
  text ".Layer_Name" at 577,-858.49 h60
M15 Courtyards Top:
  text ".Layer_Name" at 577,-858.49 h60
M16 Courtyards Bottom:
  text ".Layer_Name" at 577,-858.49 h60
Drill Drawing:
  circle w10: c5348.9,3003.91 r22.14
  lines w10: 5326.76,2882.15 5348.9,2893.22 5371.04,2882.15 5359.97,2904.29 5371.04,2926.43 5348.9,2915.36 5326.76,2926.43 5337.83,2904.29 5326.76,2882.15 ; 5326.76,3103.54 5348.9,3081.4 5371.04,3103.54 5348.9,3125.67 5326.76,3103.54 ; 5326.76,3192.09 5337.83,3192.09 5348.9,3181.02 5359.97,3192.09 5371.04,3192.09 5359.97,3203.16 5371.04,3214.23 5359.97,3214.23 5348.9,3225.3 5337.83,3214.23 5326.76,3214.23 5337.83,3203.16 5326.76,3192.09 ; 5326.76,3280.64 5371.04,3280.64 5371.04,3324.92 5326.76,3324.92 5326.76,3280.64
  lines w12: 5286,2852.27 8398.94,2852.27 ; 5286,3350.38 8398.94,3350.38 ; 5601.63,2752.64 5601.63,3450 ; 5918.82,2752.64 5918.82,3450 ; 6540.56,2752.64 6540.56,3450 ; 6784.88,2752.64 6784.88,3450 ; 7145.22,2752.64 7145.22,3450 ; 7854.73,2752.64 7854.73,3450 ; 5286,2752.64 8398.94,2752.64 8398.94,3450 5286,3450 5286,2752.64
  text "Symbol" at 5345.77,3380.26 h72
  text "Quantity" at 5631.52,3380.26 h72
  text "Finished Hole Size" at 5948.7,3380.26 h72
  text "Plated" at 6570.45,3380.26 h72
  text "Hole Type" at 6814.77,3380.26 h72
  text "Drill Layer Pair" at 7175.11,3380.26 h72
  text "Hole Tolerance" at 7884.62,3380.26 h72
  text "9" at 5631.52,3280.64 h60
  text "7.87mil (0.200mm)" at 5948.7,3280.64 h60
  text "PTH" at 6570.45,3280.64 h60
  text "Round" at 6814.77,3280.64 h60
  text "Top Layer - Bottom Layer" at 7175.11,3280.64 h60
  text "24" at 5631.52,3181.02 h60
  text "11.81mil (0.300mm)" at 5948.7,3181.02 h60
  text "PTH" at 6570.45,3181.02 h60
  text "Round" at 6814.77,3181.02 h60
  text "Top Layer - Bottom Layer" at 7175.11,3181.02 h60
  text "6" at 5631.52,3081.4 h60
  text "15.00mil (0.381mm)" at 5948.7,3081.4 h60
  text "PTH" at 6570.45,3081.4 h60
  text "Round" at 6814.77,3081.4 h60
  text "Top Layer - Bottom Layer" at 7175.11,3081.4 h60
  text "2" at 5631.52,2981.77 h60
  text "19.69mil (0.500mm)" at 5948.7,2981.77 h60
  text "PTH" at 6570.45,2981.77 h60
  text "Round" at 6814.77,2981.77 h60
  text "Top Layer - Bottom Layer" at 7175.11,2981.77 h60
  text "10" at 5631.52,2882.15 h60
  text "40.16mil (1.020mm)" at 5948.7,2882.15 h60
  text "PTH" at 6570.45,2882.15 h60
  text "Round" at 6814.77,2882.15 h60
  text "Top Layer - Bottom Layer" at 7175.11,2882.15 h60
  text "51 Total" at 5631.52,2782.53 h60
  text ".Layer_Name" at 577,-858.49 h60
M17 Embedded Cavity:
  text ".Layer_Name" at 577,-858.49 h60
M18 Embedded Assembly:
  text ".Layer_Name" at 577,-858.49 h60
M19 Embedded Keepout:
  text ".Layer_Name" at 577,-858.49 h60

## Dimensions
0,-400 to 1000,-400 on M2 Board Dimensions
0,0 to 140,1420 on M2 Board Dimensions
0,0 to 1310,130 on M2 Board Dimensions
